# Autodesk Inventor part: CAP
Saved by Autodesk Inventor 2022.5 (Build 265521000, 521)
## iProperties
Created: 2024-11
Part Number: CAP
Material: Generic
Description: NOT SPECIFIED
Document SubType Name: Modeling
Designer: AdminForWorker
Density: 1 g/cm^3
Appearance: Default
Title: CAP
Author: AdminForWorker
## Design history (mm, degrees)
feature "Body1"
body "Solid1"
